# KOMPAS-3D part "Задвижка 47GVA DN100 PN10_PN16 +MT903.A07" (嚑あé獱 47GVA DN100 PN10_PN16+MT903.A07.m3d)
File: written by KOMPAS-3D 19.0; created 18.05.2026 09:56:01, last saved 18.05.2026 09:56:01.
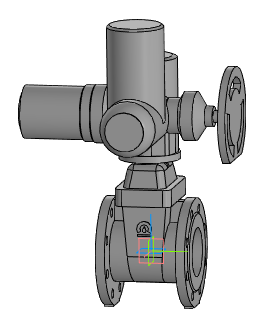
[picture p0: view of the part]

Document properties: Автор: Энергия; Полное имя файла: ..\Задвижка 47GVA DN50_DN1000+MT903.A\Задвижка 47GVA DN100 PN10_PN16+MT903.A07.a3d

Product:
- Part/product: Задвижка 47GVA DN100 PN10_PN16 +MT903.A07
    Масса: 94.6311
  - Body: Электропривод МТ903.А07 без блока управления
      Масса: 65.4738
  - Body: Задвижка 47GVA DN100 PN10_PN16 без исполнит. мех.
      Масса: 29.1572

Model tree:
1. Операция без истории:1
2. Операция без истории:2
